(* Logix 5000 project; controller EFlo_iQ_Controller vendor 1 type 14 code 74 rev 20.12; software revision 20.01; part 2 of 2 *)
(* tags used below, declared in another part *)
   Heat_Module_Two : Heat_Module;
(* MainProgram, continued *)

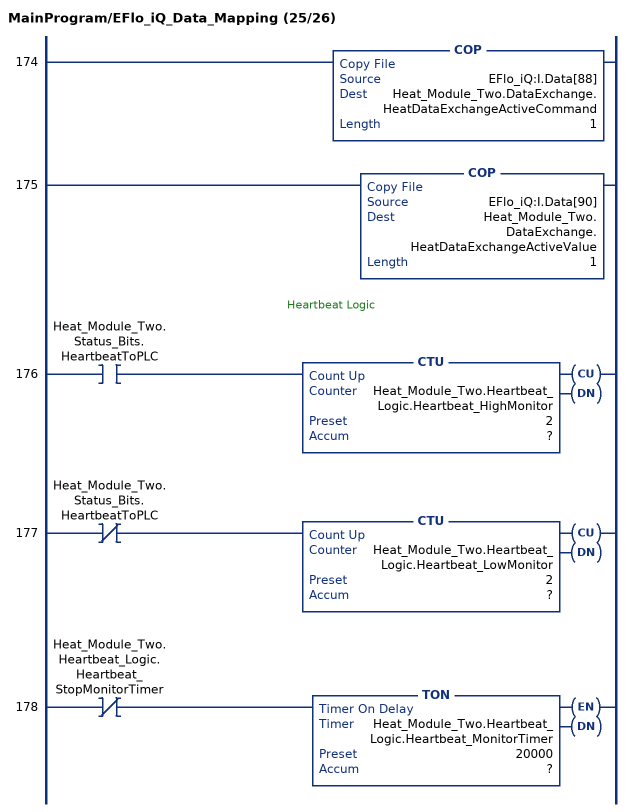
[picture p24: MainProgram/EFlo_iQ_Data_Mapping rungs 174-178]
   174: COP(EFlo_iQ:I.Data[88],Heat_Module_Two.DataExchange.HeatDataExchangeActiveCommand,1);
   175: COP(EFlo_iQ:I.Data[90],Heat_Module_Two.DataExchange.HeatDataExchangeActiveValue,1);
   // Heartbeat Logic
   176: XIC(Heat_Module_Two.Status_Bits.HeartbeatToPLC)CTU(Heat_Module_Two.Heartbeat_Logic.Heartbeat_HighMonitor,?,?);
   177: XIO(Heat_Module_Two.Status_Bits.HeartbeatToPLC)CTU(Heat_Module_Two.Heartbeat_Logic.Heartbeat_LowMonitor,?,?);
   178: XIO(Heat_Module_Two.Heartbeat_Logic.Heartbeat_StopMonitorTimer)TON(Heat_Module_Two.Heartbeat_Logic.Heartbeat_MonitorTimer,?,?);
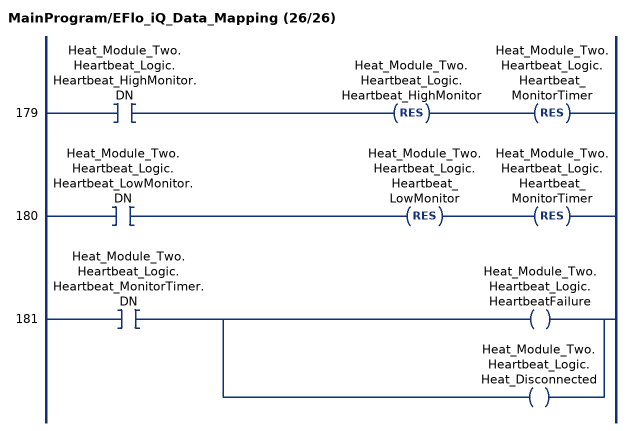
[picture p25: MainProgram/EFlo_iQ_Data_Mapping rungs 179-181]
   179: XIC(Heat_Module_Two.Heartbeat_Logic.Heartbeat_HighMonitor.DN)RES(Heat_Module_Two.Heartbeat_Logic.Heartbeat_HighMonitor)RES(Heat_Module_Two.Heartbeat_Logic.Heartbeat_MonitorTimer);
   180: XIC(Heat_Module_Two.Heartbeat_Logic.Heartbeat_LowMonitor.DN)RES(Heat_Module_Two.Heartbeat_Logic.Heartbeat_LowMonitor)RES(Heat_Module_Two.Heartbeat_Logic.Heartbeat_MonitorTimer);
   181: XIC(Heat_Module_Two.Heartbeat_Logic.Heartbeat_MonitorTimer.DN)[OTE(Heat_Module_Two.Heartbeat_Logic.HeartbeatFailure) ,OTE(Heat_Module_Two.Heartbeat_Logic.Heat_Disconnected) ];
END_ROUTINE

ROUTINE MainRoutine   (* ladder *)
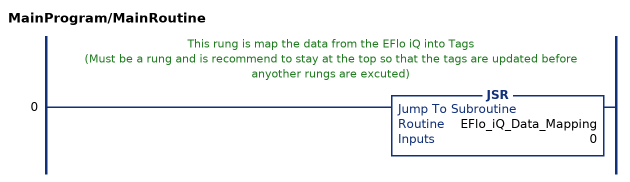
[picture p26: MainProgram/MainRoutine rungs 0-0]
   // This rung is map the data from the EFlo iQ into Tags
   // (Must be a rung and is recommend to stay at the top so that the tags are updated before anyother rungs are excuted)
   0: JSR(EFlo_iQ_Data_Mapping,0);
END_ROUTINE
END_PROGRAM
